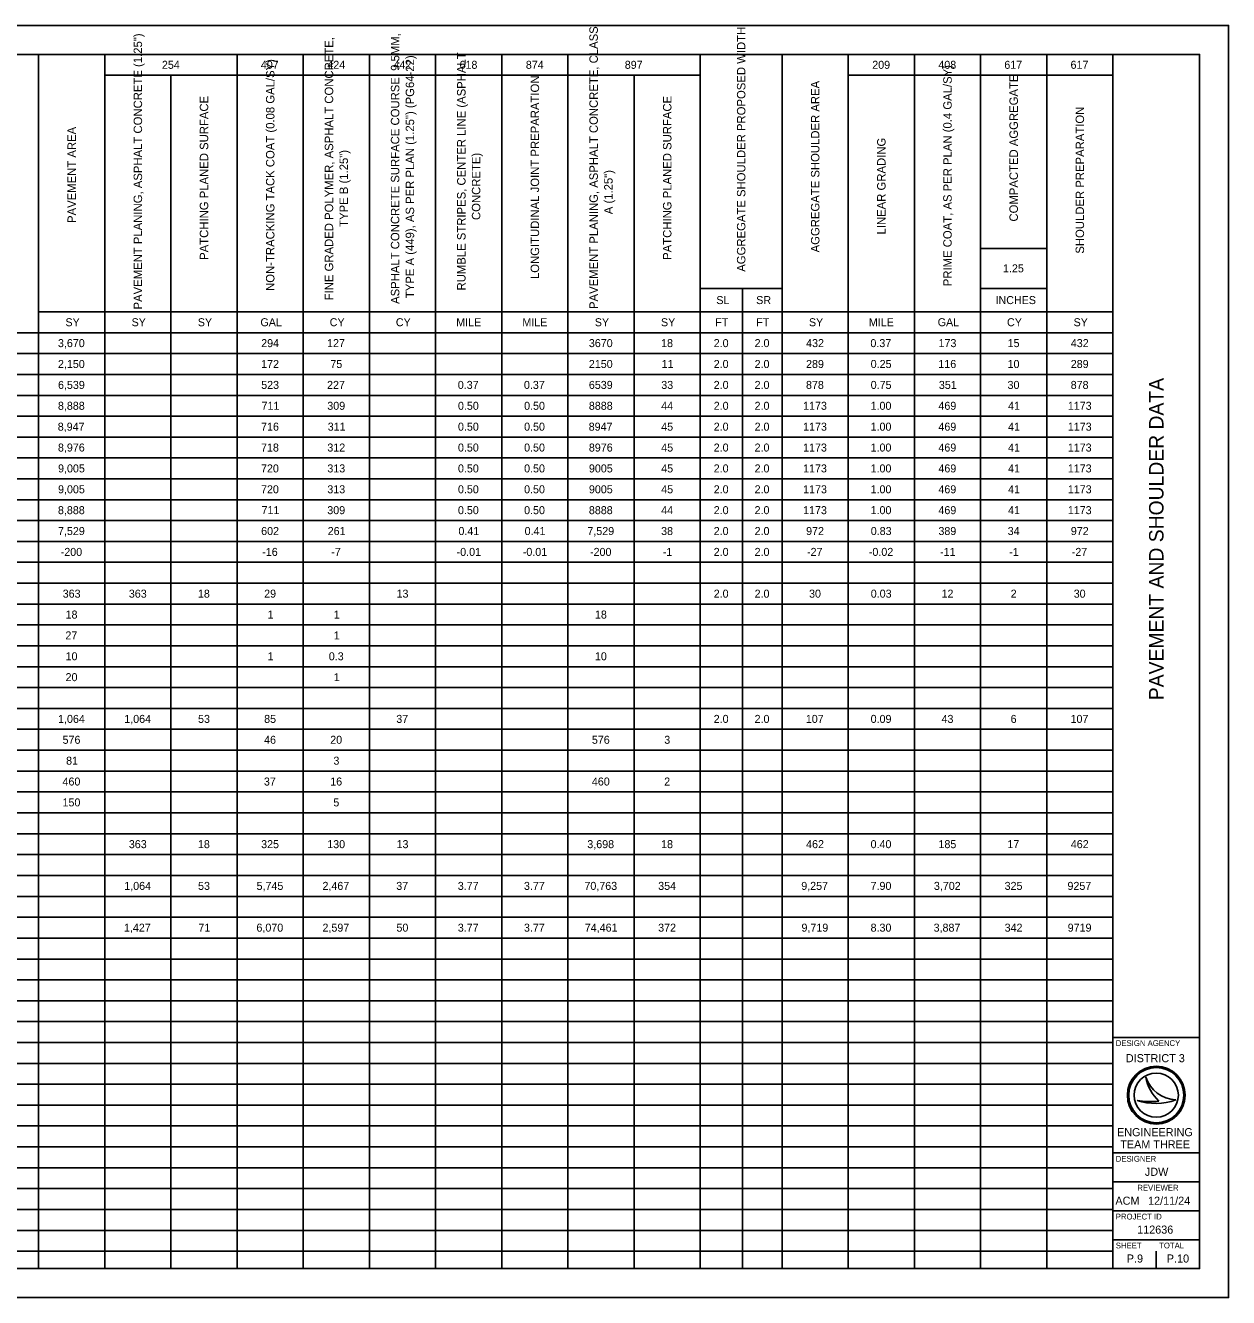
# Model space of a CAD drawing. Extents: x 0 to 34, y 0 to 22.
# Drawn here: x 13.19 to 34, y 0 to 22 of the extents above; entities that cross this region are included whole.
import ezdxf

# ---------------------------------------------------------------- set-up
doc = ezdxf.new("R2010")
doc.units = 0
for name, color, linetype in [('GM_X_County', 7, 'Continuous'), ('GM_X_Minor_Lake', 7, 'Continuous'), ('GM_X_Minor_Lake_Text', 7, 'Continuous'), ('GM_X_Minor_River_Text', 7, 'Continuous')]:
    doc.layers.add(name, color=color, linetype=linetype)

msp = doc.modelspace()

# ---------------------------------------------------------------- linework, layer by layer
at = {"layer": 'GM_X_County'}
msp.add_lwpolyline([(0, 0), (34, 0), (34, 22), (0, 22)], close=True, dxfattribs=at)
at = {"layer": 'GM_X_Minor_Lake'}
for p, q in [((1.5, 21.5), (32, 21.5)), ((13.42, 21.5), (13.42, 0.5)), ((14.565, 21.5), (14.565, 0.5)), ((16.853, 21.5), (16.853, 0.5)), ((17.998, 21.5), (17.998, 0.5)), ((19.142, 21.5), (19.142, 0.5)), ((20.286, 21.5), (20.286, 0.5)), ((21.431, 21.5), (21.431, 0.5)), ((22.575, 21.5), (22.575, 0.5)), ((24.864, 21.5), (24.864, 0.5)), ((26.278, 21.5), (26.278, 0.5)), ((27.423, 21.5), (27.423, 0.5)), ((28.567, 21.5), (28.567, 0.5)), ((29.711, 21.5), (29.711, 0.5)), ((30.856, 21.5), (30.856, 0.5)), ((32, 21.5), (32, 0.5)), ((14.565, 21.139), (24.864, 21.139)), ((15.709, 21.139), (15.709, 0.5)), ((23.719, 21.139), (23.719, 0.5)), ((27.423, 21.139), (32, 21.139)), ((29.711, 18.145), (30.856, 18.145)), ((24.864, 17.453), (26.278, 17.453)), ((25.595, 17.453), (25.595, 0.5)), ((29.711, 17.453), (30.856, 17.453)), ((13.42, 17.047), (32, 17.047)), ((1.5, 16.686), (32, 16.686)), ((1.5, 16.325), (32, 16.325)), ((1.5, 15.964), (32, 15.964)), ((1.5, 15.603), (32, 15.603)), ((1.5, 15.242), (32, 15.242)), ((1.5, 14.881), (32, 14.881)), ((1.5, 14.52), (32, 14.52)), ((1.5, 14.159), (32, 14.159)), ((1.5, 13.798), (32, 13.798)), ((1.5, 13.437), (32, 13.437)), ((1.5, 13.076), (32, 13.076)), ((1.5, 12.715), (32, 12.715)), ((1.5, 12.354), (32, 12.354)), ((1.5, 11.993), (32, 11.993)), ((1.5, 11.632), (32, 11.632)), ((1.5, 11.271), (32, 11.271)), ((1.5, 10.91), (32, 10.91)), ((1.5, 10.549), (32, 10.549)), ((1.5, 10.188), (32, 10.188)), ((1.5, 9.827), (32, 9.827)), ((1.5, 9.466), (32, 9.466)), ((1.5, 9.105), (32, 9.105)), ((1.5, 8.744), (32, 8.744)), ((1.5, 8.383), (32, 8.383)), ((1.5, 8.021), (32, 8.021)), ((1.5, 7.66), (32, 7.66)), ((1.5, 7.299), (32, 7.299)), ((1.5, 6.938), (32, 6.938)), ((1.5, 6.577), (32, 6.577)), ((1.5, 6.216), (32, 6.216)), ((1.5, 5.855), (32, 5.855)), ((1.5, 5.494), (32, 5.494)), ((1.5, 5.133), (32, 5.133)), ((1.5, 4.772), (32, 4.772)), ((1.5, 4.411), (32, 4.411)), ((1.5, 4.05), (32, 4.05)), ((1.5, 3.689), (32, 3.689)), ((1.5, 3.328), (32, 3.328)), ((1.5, 2.967), (32, 2.967)), ((1.5, 2.606), (32, 2.606)), ((1.5, 2.245), (32, 2.245)), ((1.5, 1.884), (32, 1.884)), ((1.5, 1.523), (32, 1.523)), ((1.5, 1.162), (32, 1.162)), ((1.5, 0.801), (32, 0.801)), ((1.5, 0.5), (32, 0.5))]:
    msp.add_line(p, q, dxfattribs=at)
at = {"layer": 'GM_X_Minor_Lake_Text'}
for p, q in [((32.567, 3.81), (32.567, 3.81)), ((32.417, 3.41), (32.417, 3.41)), ((32.75, 3.5), (32.75, 3.5)), ((33.087, 3.419), (33.087, 3.419)), ((32.375, 0.675), (32.375, 0.675)), ((32.75, 0.5), (32.75, 0.8))]:
    msp.add_line(p, q, dxfattribs=at)
for radius in [0.5, 0.477, 0.477, 0.382]:
    msp.add_circle((32.75, 3.5), radius, dxfattribs=at)
for centre, radius, start, end in [((33.116, 3.998), 0.58, 198.9257, 198.9319), ((33.347, 3.97), 0.796, 191.6379, 191.6421), ((33.116, 3.998), 0.58, 198.9319, 267.1657), ((33.347, 3.97), 0.796, 191.6421, 226.0947), ((32.739, 4.37), 1.013, 251.4576, 290.0832), ((32.648, 4.654), 1.266, 259.4964, 259.4995), ((32.739, 4.37), 1.013, 251.4527, 251.4576), ((32.648, 4.654), 1.266, 259.4995, 276.6672)]:
    msp.add_arc(centre, radius, start, end, dxfattribs=at)
at = {"layer": 'GM_X_Minor_River_Text'}
for p, q in [((32, 0.5), (32, 21.5)), ((32, 4.5), (33.5, 4.5)), ((32, 2.5), (33.5, 2.5)), ((32, 2), (33.5, 2)), ((32, 1.5), (33.5, 1.5)), ((32, 1), (33.5, 1))]:
    msp.add_line(p, q, dxfattribs=at)
msp.add_lwpolyline([(1.5, 21.5), (33.5, 21.5), (33.5, 0.5), (1.5, 0.5)], close=True, dxfattribs=at)

# ---------------------------------------------------------------- texts
at = {"layer": 'GM_X_Minor_Lake'}
for s, height, p in [('PAVEMENT PLANING, ASPHALT CONCRETE (1.25")', 0.14622, (15.21, 17.088)), ('FINE GRADED POLYMER, ASPHALT CONCRETE, ', 0.14622, (18.515, 17.246)), ('ASPHALT CONCRETE SURFACE COURSE, 9.5MM, ', 0.14622, (19.659, 17.184)), ('PAVEMENT PLANING, ASPHALT CONCRETE, CLASS ', 0.14622, (23.092, 17.096)), ('AGGREGATE SHOULDER PROPOSED WIDTH', 0.14622, (25.644, 17.74)), ('NON-TRACKING TACK COAT (0.08 GAL/SY)', 0.14622, (17.499, 17.409)), ('TYPE A (449), AS PER PLAN (1.25") (PG64-22)', 0.14622, (19.915, 17.284)), ('RUMBLE STRIPES, CENTER LINE (ASPHALT ', 0.14622, (20.804, 17.417)), ('PRIME COAT, AS PER PLAN (0.4 GAL/SY)', 0.14622, (29.212, 17.49)), ('COMPACTED AGGREGATE', 0.14622, (30.357, 18.608)), ('LONGITUDINAL JOINT PREPARATION', 0.14622, (22.076, 17.614)), ('AGGREGATE SHOULDER AREA', 0.14622, (26.924, 18.075)), ('PATCHING PLANED SURFACE', 0.14622, (16.354, 17.946)), ('PATCHING PLANED SURFACE', 0.14622, (24.365, 17.946)), ('SHOULDER PREPARATION', 0.14622, (31.501, 18.053)), ('PAVEMENT AREA', 0.14622, (14.066, 18.584)), ('LINEAR GRADING', 0.14622, (28.068, 18.385)), ('TYPE B (1.25")', 0.14622, (18.771, 18.517)), ('CONCRETE)', 0.1462, (21.06, 18.635)), ('A (1.25")', 0.1462, (23.348, 18.735))]:
    msp.add_text(s, height=height, rotation=90, dxfattribs=at).set_placement(p)
for s, height, p in [('254', 0.1384, (15.553, 21.25)), ('407', 0.1384, (17.264, 21.25)), ('424', 0.1384, (18.414, 21.25)), ('442', 0.1384, (19.558, 21.25)), ('618', 0.1384, (20.7, 21.25)), ('874', 0.1384, (21.847, 21.25)), ('897', 0.1384, (23.558, 21.25)), ('209', 0.1384, (27.838, 21.25)), ('408', 0.1384, (28.981, 21.25)), ('617', 0.1384, (30.122, 21.25)), ('617', 0.1384, (31.267, 21.25)), ('1.25', 0.1384, (30.099, 17.73)), ('SL', 0.1384, (25.141, 17.181)), ('SR', 0.1384, (25.831, 17.181)), ('INCHES', 0.1384, (29.97, 17.181)), ('SY', 0.1384, (13.885, 16.798)), ('SY', 0.1384, (15.029, 16.798)), ('SY', 0.1384, (16.174, 16.798)), ('GAL', 0.1384, (17.257, 16.798)), ('CY', 0.1384, (18.455, 16.798)), ('CY', 0.1384, (19.599, 16.798)), ('MILE', 0.1384, (20.643, 16.798)), ('MILE', 0.1384, (21.787, 16.798)), ('SY', 0.1384, (23.04, 16.798)), ('SY', 0.1384, (24.184, 16.798)), ('FT', 0.1384, (25.123, 16.798)), ('FT', 0.1384, (25.831, 16.798)), ('SY', 0.1384, (26.743, 16.798)), ('MILE', 0.1384, (27.779, 16.798)), ('GAL', 0.1384, (28.97, 16.798)), ('CY', 0.1384, (30.169, 16.798)), ('SY', 0.1384, (31.32, 16.798)), ('3,670', 0.1384, (13.755, 16.437)), ('294', 0.1384, (17.27, 16.437)), ('127', 0.1384, (18.409, 16.437)), ('3670', 0.1384, (22.937, 16.437)), ('18', 0.1384, (24.186, 16.437)), ('2.0', 0.1384, (25.096, 16.437)), ('2.0', 0.1384, (25.803, 16.437)), ('432', 0.1384, (26.694, 16.437)), ('0.37', 0.1384, (27.806, 16.437)), ('173', 0.1384, (28.984, 16.437)), ('15', 0.1384, (30.179, 16.437)), ('432', 0.1384, (31.272, 16.437)), ('2,150', 0.1384, (13.755, 16.076)), ('172', 0.1384, (17.269, 16.076)), ('75', 0.1384, (18.466, 16.076)), ('2150', 0.1384, (22.937, 16.076)), ('11', 0.1384, (24.195, 16.076)), ('2.0', 0.1384, (25.096, 16.076)), ('2.0', 0.1384, (25.803, 16.076)), ('289', 0.1384, (26.693, 16.076)), ('0.25', 0.1384, (27.811, 16.076)), ('116', 0.1384, (28.981, 16.076)), ('10', 0.1384, (30.178, 16.076)), ('289', 0.1384, (31.271, 16.076)), ('6,539', 0.1384, (13.756, 15.714)), ('523', 0.1384, (17.27, 15.714)), ('227', 0.1384, (18.409, 15.714)), ('0.37', 0.1384, (20.67, 15.714)), ('0.37', 0.1384, (21.814, 15.714)), ('6539', 0.1384, (22.937, 15.714)), ('33', 0.1384, (24.189, 15.714)), ('2.0', 0.1384, (25.096, 15.714)), ('2.0', 0.1384, (25.803, 15.714)), ('878', 0.1384, (26.692, 15.714)), ('0.75', 0.1384, (27.811, 15.714)), ('351', 0.1384, (28.99, 15.714)), ('30', 0.1384, (30.178, 15.714)), ('878', 0.1384, (31.27, 15.714)), ('8,888', 0.1384, (13.755, 15.353)), ('711', 0.1384, (17.276, 15.353)), ('309', 0.1384, (18.413, 15.353)), ('0.50', 0.1384, (20.673, 15.353)), ('0.50', 0.1384, (21.817, 15.353)), ('8888', 0.1384, (22.937, 15.353)), ('44', 0.1384, (24.188, 15.353)), ('2.0', 0.1384, (25.096, 15.353)), ('2.0', 0.1384, (25.803, 15.353)), ('1173', 0.1384, (26.642, 15.353)), ('1.00', 0.1384, (27.809, 15.353)), ('469', 0.1384, (28.982, 15.353)), ('41', 0.1384, (30.187, 15.353)), ('1173', 0.1384, (31.22, 15.353)), ('8,947', 0.1384, (13.752, 14.992)), ('716', 0.1384, (17.268, 14.992)), ('311', 0.1384, (18.42, 14.992)), ('0.50', 0.1384, (20.673, 14.992)), ('0.50', 0.1384, (21.817, 14.992)), ('8947', 0.1384, (22.934, 14.992)), ('45', 0.1384, (24.188, 14.992)), ('2.0', 0.1384, (25.096, 14.992)), ('2.0', 0.1384, (25.803, 14.992)), ('1173', 0.1384, (26.642, 14.992)), ('1.00', 0.1384, (27.809, 14.992)), ('469', 0.1384, (28.982, 14.992)), ('41', 0.1384, (30.187, 14.992)), ('1173', 0.1384, (31.22, 14.992)), ('8,976', 0.1384, (13.755, 14.631)), ('718', 0.1384, (17.267, 14.631)), ('312', 0.1384, (18.414, 14.631)), ('0.50', 0.1384, (20.673, 14.631)), ('0.50', 0.1384, (21.817, 14.631)), ('8976', 0.1384, (22.937, 14.631)), ('45', 0.1384, (24.188, 14.631)), ('2.0', 0.1384, (25.096, 14.631)), ('2.0', 0.1384, (25.803, 14.631)), ('1173', 0.1384, (26.642, 14.631)), ('1.00', 0.1384, (27.809, 14.631)), ('469', 0.1384, (28.982, 14.631)), ('41', 0.1384, (30.187, 14.631)), ('1173', 0.1384, (31.22, 14.631)), ('9,005', 0.1384, (13.757, 14.27)), ('720', 0.1384, (17.267, 14.27)), ('313', 0.1384, (18.414, 14.27)), ('0.50', 0.1384, (20.673, 14.27)), ('0.50', 0.1384, (21.817, 14.27)), ('9005', 0.1384, (22.938, 14.27)), ('45', 0.1384, (24.188, 14.27)), ('2.0', 0.1384, (25.096, 14.27)), ('2.0', 0.1384, (25.803, 14.27)), ('1173', 0.1384, (26.642, 14.27)), ('1.00', 0.1384, (27.809, 14.27)), ('469', 0.1384, (28.982, 14.27)), ('41', 0.1384, (30.187, 14.27)), ('1173', 0.1384, (31.22, 14.27)), ('9,005', 0.1384, (13.757, 13.909)), ('720', 0.1384, (17.267, 13.909)), ('313', 0.1384, (18.414, 13.909)), ('0.50', 0.1384, (20.673, 13.909)), ('0.50', 0.1384, (21.817, 13.909)), ('9005', 0.1384, (22.938, 13.909)), ('45', 0.1384, (24.188, 13.909)), ('2.0', 0.1384, (25.096, 13.909)), ('2.0', 0.1384, (25.803, 13.909)), ('1173', 0.1384, (26.642, 13.909)), ('1.00', 0.1384, (27.809, 13.909)), ('469', 0.1384, (28.982, 13.909)), ('41', 0.1384, (30.187, 13.909)), ('1173', 0.1384, (31.22, 13.909)), ('8,888', 0.1384, (13.755, 13.548)), ('711', 0.1384, (17.276, 13.548)), ('309', 0.1384, (18.413, 13.548)), ('0.50', 0.1384, (20.673, 13.548)), ('0.50', 0.1384, (21.817, 13.548)), ('8888', 0.1384, (22.937, 13.548)), ('44', 0.1384, (24.188, 13.548)), ('2.0', 0.1384, (25.096, 13.548)), ('2.0', 0.1384, (25.803, 13.548)), ('1173', 0.1384, (26.642, 13.548)), ('1.00', 0.1384, (27.809, 13.548)), ('469', 0.1384, (28.982, 13.548)), ('41', 0.1384, (30.187, 13.548)), ('1173', 0.1384, (31.22, 13.548)), ('7,529', 0.1384, (13.756, 13.187)), ('602', 0.1384, (17.269, 13.187)), ('261', 0.1384, (18.42, 13.187)), ('0.41', 0.1384, (20.681, 13.187)), ('0.41', 0.1384, (21.826, 13.187)), ('7,529', 0.1384, (22.911, 13.187)), ('38', 0.1384, (24.186, 13.187)), ('2.0', 0.1384, (25.096, 13.187)), ('2.0', 0.1384, (25.803, 13.187)), ('972', 0.1384, (26.694, 13.187)), ('0.83', 0.1384, (27.812, 13.187)), ('389', 0.1384, (28.982, 13.187)), ('34', 0.1384, (30.18, 13.187)), ('972', 0.1384, (31.272, 13.187)), ('-200', 0.1384, (13.803, 12.826)), ('-16', 0.1384, (17.288, 12.826)), ('-7', 0.1384, (18.482, 12.826)), ('-0.01', 0.1384, (20.65, 12.826)), ('-0.01', 0.1384, (21.794, 12.826)), ('-200', 0.1384, (22.957, 12.826)), ('-1', 0.1384, (24.215, 12.826)), ('2.0', 0.1384, (25.096, 12.826)), ('2.0', 0.1384, (25.803, 12.826)), ('-27', 0.1384, (26.71, 12.826)), ('-0.02', 0.1384, (27.779, 12.826)), ('-11', 0.1384, (29.01, 12.826)), ('-1', 0.1384, (30.207, 12.826)), ('-27', 0.1384, (31.288, 12.826)), ('363', 0.1384, (13.837, 12.104)), ('363', 0.1384, (14.981, 12.104)), ('18', 0.1384, (16.176, 12.104)), ('29', 0.1384, (17.321, 12.104)), ('13', 0.1384, (19.611, 12.104)), ('2.0', 0.1384, (25.096, 12.104)), ('2.0', 0.1384, (25.803, 12.104)), ('30', 0.1384, (26.745, 12.104)), ('0.03', 0.1384, (27.812, 12.104)), ('12', 0.1384, (29.036, 12.104)), ('2', 0.138, (30.232, 12.104)), ('30', 0.1384, (31.322, 12.104)), ('18', 0.1384, (13.887, 11.743)), ('1', 0.138, (17.381, 11.743)), ('1', 0.138, (18.525, 11.743)), ('18', 0.1384, (23.042, 11.743)), ('27', 0.1384, (13.884, 11.382)), ('1', 0.138, (18.525, 11.382)), ('10', 0.1384, (13.887, 11.021)), ('1', 0.138, (17.381, 11.021)), ('0.3', 0.1384, (18.439, 11.021)), ('10', 0.1384, (23.042, 11.021)), ('20', 0.1384, (13.887, 10.66)), ('1', 0.138, (18.525, 10.66)), ('1,064', 0.1384, (13.757, 9.938)), ('1,064', 0.1384, (14.902, 9.938)), ('53', 0.1384, (16.178, 9.938)), ('85', 0.1384, (17.321, 9.938)), ('37', 0.1384, (19.606, 9.938)), ('2.0', 0.1384, (25.096, 9.938)), ('2.0', 0.1384, (25.803, 9.938)), ('107', 0.1384, (26.689, 9.938)), ('0.09', 0.1384, (27.81, 9.938)), ('43', 0.1384, (29.036, 9.938)), ('6', 0.138, (30.231, 9.938)), ('107', 0.1384, (31.267, 9.938)), ('576', 0.1384, (13.835, 9.577)), ('46', 0.1384, (17.32, 9.577)), ('20', 0.1384, (18.464, 9.577)), ('576', 0.1384, (22.989, 9.577)), ('3', 0.138, (24.241, 9.577)), ('81', 0.1384, (13.896, 9.216)), ('3', 0.138, (18.519, 9.216)), ('460', 0.1384, (13.834, 8.855)), ('37', 0.1384, (17.317, 8.855)), ('16', 0.1384, (18.464, 8.855)), ('460', 0.1384, (22.989, 8.855)), ('2', 0.138, (24.24, 8.855)), ('150', 0.1384, (13.834, 8.494)), ('5', 0.138, (18.518, 8.494)), ('363', 0.1384, (14.981, 7.772)), ('18', 0.1384, (16.176, 7.772)), ('325', 0.1384, (17.269, 7.772)), ('130', 0.1384, (18.412, 7.772)), ('13', 0.1384, (19.611, 7.772)), ('3,698', 0.1384, (22.91, 7.772)), ('18', 0.1384, (24.186, 7.772)), ('462', 0.1384, (26.694, 7.772)), ('0.40', 0.1384, (27.809, 7.772)), ('185', 0.1384, (28.983, 7.772)), ('17', 0.1384, (30.175, 7.772)), ('462', 0.1384, (31.272, 7.772)), ('1,064', 0.1384, (14.902, 7.05)), ('53', 0.1384, (16.178, 7.05)), ('5,745', 0.1384, (17.19, 7.05)), ('2,467', 0.1384, (18.33, 7.05)), ('37', 0.1384, (19.606, 7.05)), ('3.77', 0.1384, (20.67, 7.05)), ('3.77', 0.1384, (21.814, 7.05)), ('70,763', 0.1384, (22.86, 7.05)), ('354', 0.1384, (24.136, 7.05)), ('9,257', 0.1384, (26.61, 7.05)), ('7.90', 0.1384, (27.809, 7.05)), ('3,702', 0.1384, (28.904, 7.05)), ('325', 0.1384, (30.127, 7.05)), ('9257', 0.1384, (31.214, 7.05)), ('1,427', 0.1384, (14.897, 6.328)), ('71', 0.1384, (16.184, 6.328)), ('6,070', 0.1384, (17.188, 6.328)), ('2,597', 0.1384, (18.33, 6.328)), ('50', 0.1384, (19.609, 6.328)), ('3.77', 0.1384, (20.67, 6.328)), ('3.77', 0.1384, (21.814, 6.328)), ('74,461', 0.1384, (22.866, 6.328)), ('372', 0.1384, (24.135, 6.328)), ('9,719', 0.1384, (26.614, 6.328)), ('8.30', 0.1384, (27.809, 6.328)), ('3,887', 0.1384, (28.899, 6.328)), ('342', 0.1384, (30.127, 6.328)), ('9719', 0.1384, (31.218, 6.328))]:
    msp.add_text(s, height=height, dxfattribs=at).set_placement(p)
at = {"layer": 'GM_X_Minor_Lake_Text'}
msp.add_text('PAVEMENT AND SHOULDER DATA', height=0.25, rotation=90, dxfattribs=at).set_placement((32.875, 10.331))
for s, height, p in [('DESIGN AGENCY', 0.1, (32.05, 4.35)), ('DISTRICT 3', 0.14, (32.224, 4.07)), ('ENGINEERING', 0.14, (32.071, 2.79)), ('TEAM THREE', 0.14, (32.127, 2.58)), ('DESIGNER', 0.1, (32.05, 2.35)), ('JDW', 0.14, (32.553, 2.105)), ('REVIEWER', 0.1, (32.422, 1.85)), ('ACM', 0.14, (32.043, 1.605)), ('12/11/24', 0.14, (32.608, 1.605)), ('PROJECT ID', 0.1, (32.05, 1.35)), ('112636', 0.14, (32.419, 1.105)), ('SHEET', 0.1, (32.05, 0.85)), ('TOTAL', 0.1, (32.8, 0.85)), ('P.9', 0.14, (32.24, 0.605)), ('P.10', 0.14, (32.932, 0.605))]:
    msp.add_text(s, height=height, dxfattribs=at).set_placement(p)

doc.saveas('drawing.dxf')
